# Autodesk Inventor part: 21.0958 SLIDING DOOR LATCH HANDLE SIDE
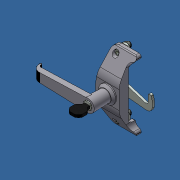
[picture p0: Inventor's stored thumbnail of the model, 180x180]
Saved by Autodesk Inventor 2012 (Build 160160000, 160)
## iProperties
Created: 2014-05
Part Number: 21.0958 SLIDING DOOR LATCH HANDLE SIDE
Material: Aluminum-6061
Document SubType Name: Modeling
Designer: Admin
Density: 2.71 g/cm^3
Mass: 286.628 g
Surface Area: 396.662 cm^2
Volume: 105.767 cm^3
Author: Admin
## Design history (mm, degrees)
node "21.0958 SLIDING DOOR LATCH HANDLE SIDE1"
node "Base1"
body "Solid1"
